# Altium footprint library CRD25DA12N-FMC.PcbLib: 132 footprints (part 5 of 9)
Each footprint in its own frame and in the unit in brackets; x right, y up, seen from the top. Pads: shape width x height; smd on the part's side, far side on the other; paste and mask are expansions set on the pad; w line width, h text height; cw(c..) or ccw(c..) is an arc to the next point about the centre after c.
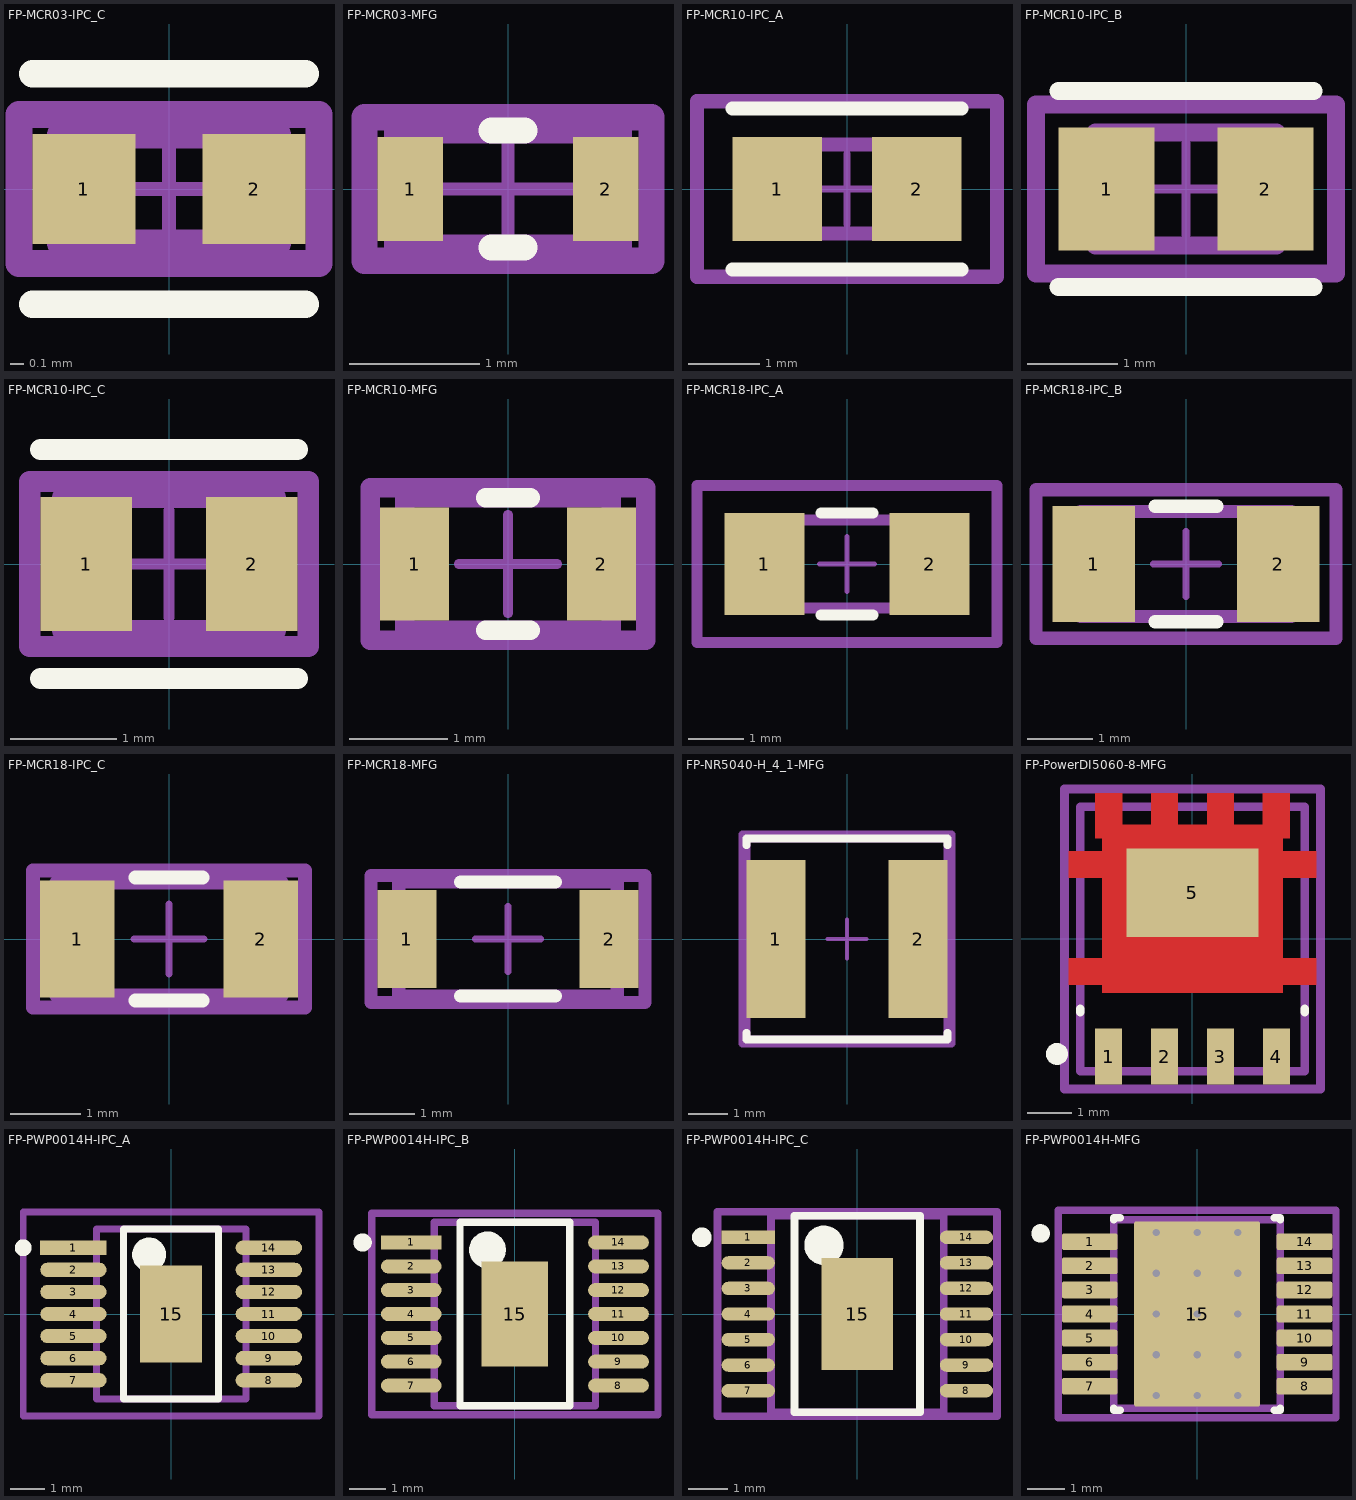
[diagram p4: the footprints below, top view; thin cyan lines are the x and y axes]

## FP-MCR03-IPC_C [mm]
pads (2):
  rect 0.758x0.812 smd paste+0 mask+0: 1(-0.627,0) 2(0.627,0)
Top Overlay:
  lines w0.2: -1.006,-0.85 1.006,-0.85 ; -1.006,0.85 1.006,0.85
Mechanical 5:
  lines w0.2: -1.106,-0.55 1.106,-0.55 1.106,0.55 -1.106,0.55 -1.106,-0.55
  text ".Designator" at 0,0.188 h1
Mechanical 13:
  lines w0.2: -0.8,-0.4 0.8,-0.4 0.8,0.4 -0.8,0.4 -0.8,-0.4
Mechanical 15:
  lines w0.2: -1.106,-0.55 1.106,-0.55 1.106,0.55 -1.106,0.55 -1.106,-0.55
Mechanical 16:
  lines w0.1: -0.5,0 0.5,0 ; 0,-0.5 0,0.5
3D body "Res_Rohm_MCR03ERTF1182_eec.STEP": height 0.25, standoff 0, extent -1.106,-0.55 1.106,0.55

## FP-MCR03-MFG [mm]
pads (2):
  rect 0.5x0.8 smd paste+0 mask+0: 1(-0.75,0) 2(0.75,0)
Top Overlay:
  lines w0.2: -0.125,-0.45 0.125,-0.45 ; -0.125,0.45 0.125,0.45
Mechanical 5:
  lines w0.2: -1.1,-0.55 -1.1,0.55 1.1,0.55 1.1,-0.55 -1.1,-0.55
  text ".Designator" at 0,0.188 h1
Mechanical 13:
  lines w0.2: -0.85,-0.45 -0.85,0.45 0.85,0.45 0.85,-0.45 -0.85,-0.45
Mechanical 15:
  lines w0.2: -1.1,-0.55 -1.1,0.55 1.1,0.55 1.1,-0.55 -1.1,-0.55
Mechanical 16:
  lines w0.1: -0.5,0 0.5,0 ; 0,-0.5 0,0.5
3D body "Res_Rohm_MCR03ERTF1182_eec.STEP": height 0.25, standoff 0, extent -1.1,-0.55 1.1,0.55

## FP-MCR10-IPC_A [mm]
pads (2):
  rect 1.258x1.462 smd paste+0 mask+0: 1(-0.977,0) 2(0.977,0)
Top Overlay:
  lines w0.2: -1.606,-1.131 1.606,-1.131 ; -1.606,1.131 1.606,1.131
Mechanical 5:
  lines w0.2: -2.106,-1.231 2.106,-1.231 2.106,1.231 -2.106,1.231 -2.106,-1.231
  text ".Designator" at 0,0.188 h1
Mechanical 13:
  lines w0.2: -1,-0.625 1,-0.625 1,0.625 -1,0.625 -1,-0.625
Mechanical 15:
  lines w0.2: -2.106,-1.231 2.106,-1.231 2.106,1.231 -2.106,1.231 -2.106,-1.231
Mechanical 16:
  lines w0.1: -0.5,0 0.5,0 ; 0,-0.5 0,0.5
3D body "Res_Rohm_MCR10ERTJ510_eec.STEP": height 0.25, standoff 0, extent -2.106,-1.231 2.106,1.231

## FP-MCR10-IPC_B [mm]
pads (2):
  rect 1.058x1.362 smd paste+0 mask+0: 1(-0.877,0) 2(0.877,0)
Top Overlay:
  lines w0.2: -1.406,-1.081 1.406,-1.081 ; -1.406,1.081 1.406,1.081
Mechanical 5:
  lines w0.2: -1.656,-0.931 1.656,-0.931 1.656,0.931 -1.656,0.931 -1.656,-0.931
  text ".Designator" at 0,0.188 h1
Mechanical 13:
  lines w0.2: -1,-0.625 1,-0.625 1,0.625 -1,0.625 -1,-0.625
Mechanical 15:
  lines w0.2: -1.656,-0.931 1.656,-0.931 1.656,0.931 -1.656,0.931 -1.656,-0.931
Mechanical 16:
  lines w0.1: -0.5,0 0.5,0 ; 0,-0.5 0,0.5
3D body "Res_Rohm_MCR10ERTJ510_eec.STEP": height 0.25, standoff 0, extent -1.656,-0.931 1.656,0.931

## FP-MCR10-IPC_C [mm]
pads (2):
  rect 0.858x1.262 smd paste+0 mask+0: 1(-0.777,0) 2(0.777,0)
Top Overlay:
  lines w0.2: -1.206,-1.075 1.206,-1.075 ; -1.206,1.075 1.206,1.075
Mechanical 5:
  lines w0.2: -1.306,-0.775 -1.306,0.775 1.306,0.775 1.306,-0.775 -1.306,-0.775
  text ".Designator" at 0,0.188 h1
Mechanical 13:
  lines w0.2: -1,-0.625 -1,0.625 1,0.625 1,-0.625 -1,-0.625
Mechanical 15:
  lines w0.2: -1.306,-0.775 -1.306,0.775 1.306,0.775 1.306,-0.775 -1.306,-0.775
Mechanical 16:
  lines w0.1: -0.5,0 0.5,0 ; 0,-0.5 0,0.5
3D body "Res_Rohm_MCR10ERTJ510_eec.STEP": height 0.25, standoff 0, extent -1.306,-0.775 1.306,0.775

## FP-MCR10-MFG [mm]
pads (2):
  rect 0.7x1.15 smd paste+0 mask+0: 1(-0.95,0) 2(0.95,0)
Top Overlay:
  lines w0.2: -0.225,-0.675 0.225,-0.675 ; -0.225,0.675 0.225,0.675
Mechanical 5:
  lines w0.2: -1.4,-0.775 -1.4,0.775 1.4,0.775 1.4,-0.775 -1.4,-0.775
  text ".Designator" at 0,0.188 h1
Mechanical 13:
  lines w0.2: -1.05,-0.675 -1.05,0.675 1.05,0.675 1.05,-0.675 -1.05,-0.675
Mechanical 15:
  lines w0.2: -1.4,-0.775 -1.4,0.775 1.4,0.775 1.4,-0.775 -1.4,-0.775
Mechanical 16:
  lines w0.1: -0.5,0 0.5,0 ; 0,-0.5 0,0.5
3D body "Res_Rohm_MCR10ERTJ510_eec.STEP": height 0.25, standoff 0, extent -1.4,-0.775 1.4,0.775

## FP-MCR18-IPC_A [mm]
pads (2):
  rect 1.456x1.858 smd paste+0 mask+0: 1(-1.501,0) 2(1.501,0)
Top Overlay:
  lines w0.2: -0.473,-0.929 0.473,-0.929 ; -0.473,0.929 0.473,0.929
Mechanical 5:
  lines w0.2: -2.729,-1.429 -2.729,1.429 2.729,1.429 2.729,-1.429 -2.729,-1.429
  text ".Designator" at 0,0.188 h1
Mechanical 13:
  lines w0.2: -1.6,-0.8 -1.6,0.8 1.6,0.8 1.6,-0.8 -1.6,-0.8
Mechanical 15:
  lines w0.2: -2.729,-1.429 -2.729,1.429 2.729,1.429 2.729,-1.429 -2.729,-1.429
Mechanical 16:
  lines w0.1: -0.5,0 0.5,0 ; 0,-0.5 0,0.5
3D body "Res_Rohm_MCR18ERTFL1R10_eec.STEP": height 0.25, standoff 0, extent -2.729,-1.429 2.729,1.429

## FP-MCR18-IPC_B [mm]
pads (2):
  rect 1.256x1.758 smd paste+0 mask+0: 1(-1.401,0) 2(1.401,0)
Top Overlay:
  lines w0.2: -0.473,-0.879 0.473,-0.879 ; -0.473,0.879 0.473,0.879
Mechanical 5:
  lines w0.2: -2.279,-1.129 -2.279,1.129 2.279,1.129 2.279,-1.129 -2.279,-1.129
  text ".Designator" at 0,0.188 h1
Mechanical 13:
  lines w0.2: -1.6,-0.8 -1.6,0.8 1.6,0.8 1.6,-0.8 -1.6,-0.8
Mechanical 15:
  lines w0.2: -2.279,-1.129 -2.279,1.129 2.279,1.129 2.279,-1.129 -2.279,-1.129
Mechanical 16:
  lines w0.1: -0.5,0 0.5,0 ; 0,-0.5 0,0.5
3D body "Res_Rohm_MCR18ERTFL1R10_eec.STEP": height 0.25, standoff 0, extent -2.279,-1.129 2.279,1.129

## FP-MCR18-IPC_C [mm]
pads (2):
  rect 1.056x1.658 smd paste+0 mask+0: 1(-1.301,0) 2(1.301,0)
Top Overlay:
  lines w0.2: -0.473,-0.875 0.473,-0.875 ; -0.473,0.875 0.473,0.875
Mechanical 5:
  lines w0.2: -1.929,-0.975 1.929,-0.975 1.929,0.975 -1.929,0.975 -1.929,-0.975
  text ".Designator" at 0,0.188 h1
Mechanical 13:
  lines w0.2: -1.6,-0.8 1.6,-0.8 1.6,0.8 -1.6,0.8 -1.6,-0.8
Mechanical 15:
  lines w0.2: -1.929,-0.975 1.929,-0.975 1.929,0.975 -1.929,0.975 -1.929,-0.975
Mechanical 16:
  lines w0.1: -0.5,0 0.5,0 ; 0,-0.5 0,0.5
3D body "Res_Rohm_MCR18ERTFL1R10_eec.STEP": height 0.25, standoff 0, extent -1.929,-0.975 1.929,0.975

## FP-MCR18-MFG [mm]
pads (2):
  rect 0.9x1.5 smd paste+0 mask+0: 1(-1.55,0) 2(1.55,0)
Top Overlay:
  lines w0.2: -0.725,-0.875 0.725,-0.875 ; -0.725,0.875 0.725,0.875
Mechanical 5:
  lines w0.2: -2.1,-0.975 -2.1,0.975 2.1,0.975 2.1,-0.975 -2.1,-0.975
  text ".Designator" at 0,0.188 h1
Mechanical 13:
  lines w0.2: -1.675,-0.875 -1.675,0.875 1.675,0.875 1.675,-0.875 -1.675,-0.875
Mechanical 15:
  lines w0.2: -2.1,-0.975 -2.1,0.975 2.1,0.975 2.1,-0.975 -2.1,-0.975
Mechanical 16:
  lines w0.1: -0.5,0 0.5,0 ; 0,-0.5 0,0.5
3D body "Res_Rohm_MCR18ERTFL1R10_eec.STEP": height 0.25, standoff 0, extent -2.1,-0.975 2.1,0.975

## FP-NR5040-H_4_1-MFG [mm]
pads (2):
  rect 1.5x4 smd paste+0 mask+0: 1(-1.8,0) 2(1.8,0)
Top Overlay:
  lines w0.2: -2.55,-2.375 -2.55,-2.55 2.55,-2.55 2.55,-2.375 ; -2.55,2.375 -2.55,2.55 2.55,2.55 2.55,2.375
Mechanical 5:
  lines w0.2: -2.65,-2.65 -2.65,2.65 2.65,2.65 2.65,-2.65 -2.65,-2.65
  text ".Designator" at 0,0.188 h1
Mechanical 13:
  lines w0.2: -2.55,-2.55 -2.55,2.55 2.55,2.55 2.55,-2.55 -2.55,-2.55
Mechanical 15:
  lines w0.2: -2.65,-2.65 -2.65,2.65 2.65,2.65 2.65,-2.65 -2.65,-2.65
Mechanical 16:
  lines w0.1: -0.5,0 0.5,0 ; 0,-0.5 0,0.5
3D body "Ind_Taiyo_Yuden_NR5040T1R5N_eec.STEP": height 0.25, standoff 0, extent -2.65,-2.65 2.65,2.65

## FP-PowerDI5060-8-MFG [mm]
pads (5):
  rect 0.61x1.27 smd paste+0 mask+0: 1(-1.905,-2.67) 2(-0.635,-2.67) 3(0.635,-2.67) 4(1.905,-2.67)
  rect 3x2 smd paste+0 mask+0: 5(0,1.05)
Top Layer:
  region: 2.05,-1.215 -2.05,-1.215 -2.05,-1.035 -2.805,-1.035 -2.805,-0.435 -2.05,-0.435 -2.05,1.39 -2.805,1.39 -2.805,1.99 -2.05,1.99 -2.05,2.285 -2.21,2.285 -2.21,3.305 -1.6,3.305 -1.6,2.595 -0.94,2.595 -0.94,3.305 -0.33,3.305 -0.33,2.595 0.33,2.595 0.33,3.305 0.94,3.305 0.94,2.595 1.6,2.595 1.6,3.305 2.21,3.305 2.21,2.285 2.05,2.285 2.05,1.99 2.805,1.99 2.805,1.39 2.05,1.39 2.05,-0.435 2.805,-0.435 2.805,-1.035 2.05,-1.035
Top Overlay:
  circle w0.25: c-3.075,-2.61 r0.125
  lines w0.2: -2.55,-1.66 -2.55,-1.59 ; 2.55,-1.66 2.55,-1.59
Mechanical 5:
  lines w0.2: -2.905,-3.405 2.905,-3.405 2.905,3.405 -2.905,3.405 -2.905,-3.405
  text ".Designator" at 0,0.188 h1
Mechanical 13:
  lines w0.2: -2.55,-3 2.55,-3 2.55,3 -2.55,3 -2.55,-3
Mechanical 15:
  lines w0.2: -2.905,-3.405 2.905,-3.405 2.905,3.405 -2.905,3.405 -2.905,-3.405
Mechanical 16:
  lines w0.1: -0.5,0 0.5,0 ; 0,-0.5 0,0.5
3D body "Trans_Diodes_DMT12H007LPS-13_eec.STEP": height 0.25, standoff 0, extent -2.905,-3.405 2.905,3.405

## FP-PWP0014H-IPC_A [mm]
pads (15):
  rect 1.955x0.421 smd paste+0 mask+0: 1(-2.875,1.95)
  rrect100% 1.955x0.421 smd paste+0 mask+0: 2(-2.875,1.3) 3(-2.875,0.65) 4(-2.875,0) 5(-2.875,-0.65) 6(-2.875,-1.3) 7(-2.875,-1.95) 8(2.875,-1.95) 9(2.875,-1.3) 10(2.875,-0.65) 11(2.875,0) 12(2.875,0.65) 13(2.875,1.3) 14(2.875,1.95)
  rect 1.82x2.86 smd paste-1000 mask+0: 15(0,0)
Top Overlay:
  circle w0.5: c-0.648,1.75 r0.25
  circle w0.25: c-4.353,1.95 r0.125
  lines w0.2: -1.398,-2.5 1.398,-2.5 1.398,2.5 -1.398,2.5 -1.398,-2.5
Top Paste:
  rectangle: -0.507,-1.027 0.507,1.027
Mechanical 5:
  lines w0.2: -4.353,-3 4.353,-3 4.353,3 -4.353,3 -4.353,-3
  text ".Designator" at 0,0.188 h1
Mechanical 13:
  lines w0.2: -2.2,-2.5 2.2,-2.5 2.2,2.5 -2.2,2.5 -2.2,-2.5
Mechanical 15:
  lines w0.2: -4.353,-3 4.353,-3 4.353,3 -4.353,3 -4.353,-3
Mechanical 16:
  lines w0.1: -0.5,0 0.5,0 ; 0,-0.5 0,0.5
3D body "IC_Texas_Instruments_ALM2402FQPWPRQ1_eec.STEP": height 0.25, standoff 0, extent -4.353,-3 4.353,3

## FP-PWP0014H-IPC_B [mm]
pads (15):
  rect 1.655x0.381 smd paste+0 mask+0: 1(-2.825,1.95)
  rrect100% 1.655x0.381 smd paste+0 mask+0: 2(-2.825,1.3) 3(-2.825,0.65) 4(-2.825,0) 5(-2.825,-0.65) 6(-2.825,-1.3) 7(-2.825,-1.95) 8(2.825,-1.95) 9(2.825,-1.3) 10(2.825,-0.65) 11(2.825,0) 12(2.825,0.65) 13(2.825,1.3) 14(2.825,1.95)
  rect 1.82x2.86 smd paste-1000 mask+0: 15(0,0)
Top Overlay:
  circle w0.5: c-0.748,1.75 r0.25
  circle w0.25: c-4.153,1.95 r0.125
  lines w0.2: -1.498,-2.5 1.498,-2.5 1.498,2.5 -1.498,2.5 -1.498,-2.5
Top Paste:
  rectangle: -0.507,-1.027 0.507,1.027
Mechanical 5:
  lines w0.2: -3.903,-2.75 3.903,-2.75 3.903,2.75 -3.903,2.75 -3.903,-2.75
  text ".Designator" at 0,0.188 h1
Mechanical 13:
  lines w0.2: -2.2,-2.5 2.2,-2.5 2.2,2.5 -2.2,2.5 -2.2,-2.5
Mechanical 15:
  lines w0.2: -3.903,-2.75 3.903,-2.75 3.903,2.75 -3.903,2.75 -3.903,-2.75
Mechanical 16:
  lines w0.1: -0.5,0 0.5,0 ; 0,-0.5 0,0.5
3D body "IC_Texas_Instruments_ALM2402FQPWPRQ1_eec.STEP": height 0.25, standoff 0, extent -3.903,-2.75 3.903,2.75

## FP-PWP0014H-IPC_C [mm]
pads (15):
  rect 1.355x0.341 smd paste+0 mask+0: 1(-2.775,1.95)
  rrect100% 1.355x0.341 smd paste+0 mask+0: 2(-2.775,1.3) 3(-2.775,0.65) 4(-2.775,0) 5(-2.775,-0.65) 6(-2.775,-1.3) 7(-2.775,-1.95) 8(2.775,-1.95) 9(2.775,-1.3) 10(2.775,-0.65) 11(2.775,0) 12(2.775,0.65) 13(2.775,1.3) 14(2.775,1.95)
  rect 1.82x2.86 smd paste-1000 mask+0: 15(0,0)
Top Overlay:
  circle w0.5: c-0.848,1.75 r0.25
  circle w0.25: c-3.953,1.95 r0.125
  lines w0.2: -1.598,-2.5 1.598,-2.5 1.598,2.5 -1.598,2.5 -1.598,-2.5
Top Paste:
  rectangle: -0.507,-1.027 0.507,1.027
Mechanical 5:
  lines w0.2: -3.553,-2.6 3.553,-2.6 3.553,2.6 -3.553,2.6 -3.553,-2.6
  text ".Designator" at 0,0.188 h1
Mechanical 13:
  lines w0.2: -2.2,-2.5 2.2,-2.5 2.2,2.5 -2.2,2.5 -2.2,-2.5
Mechanical 15:
  lines w0.2: -3.553,-2.6 3.553,-2.6 3.553,2.6 -3.553,2.6 -3.553,-2.6
Mechanical 16:
  lines w0.1: -0.5,0 0.5,0 ; 0,-0.5 0,0.5
3D body "IC_Texas_Instruments_ALM2402FQPWPRQ1_eec.STEP": height 0.25, standoff 0, extent -3.553,-2.6 3.553,2.6

## FP-PWP0014H-MFG [mm]
pads (15):
  rrect22% 1.5x0.45 smd paste+0 mask+0: 1(-2.9,1.95) 2(-2.9,1.3) 3(-2.9,0.65) 4(-2.9,0) 5(-2.9,-0.65) 6(-2.9,-1.3) 7(-2.9,-1.95) 8(2.9,-1.95) 9(2.9,-1.3) 10(2.9,-0.65) 11(2.9,0) 12(2.9,0.65) 13(2.9,1.3) 14(2.9,1.95)
  rrect3% 3.4x5 smd paste-1000 mask-1000: 15(0,0)
via 1.1,2.2 diameter 0.5 hole 0.2
via 1.1,1.1 diameter 0.5 hole 0.2
via 1.1,0 diameter 0.5 hole 0.2
via 1.1,-1.1 diameter 0.5 hole 0.2
via 1.1,-2.2 diameter 0.5 hole 0.2
via -1.1,2.2 diameter 0.5 hole 0.2
via -1.1,1.1 diameter 0.5 hole 0.2
via -1.1,0 diameter 0.5 hole 0.2
via -1.1,-1.1 diameter 0.5 hole 0.2
via -1.1,-2.2 diameter 0.5 hole 0.2
via 0,2.2 diameter 0.5 hole 0.2
via 0,1.1 diameter 0.5 hole 0.2
via 0,0 diameter 0.5 hole 0.2
via 0,-1.1 diameter 0.5 hole 0.2
via 0,-2.2 diameter 0.5 hole 0.2
Top Overlay:
  circle w0.25: c-4.225,2.175 r0.125
  lines w0.2: -2.25,-2.55 -2.25,-2.6 -2.075,-2.6 ; -2.25,2.55 -2.25,2.6 -2.075,2.6 ; 2.075,-2.6 2.25,-2.6 2.25,-2.55 ; 2.075,2.6 2.25,2.6 2.25,2.55
Top Paste:
  region: 0.91,1.38 0.91,-1.38 0.91,-1.39 0.902,-1.408 0.888,-1.422 0.87,-1.43 0.86,-1.43 -0.86,-1.43 -0.87,-1.43 -0.888,-1.422 -0.902,-1.408 -0.91,-1.39 -0.91,-1.38 -0.91,1.38 -0.91,1.39 -0.902,1.408 -0.888,1.422 -0.87,1.43 -0.86,1.43 0.86,1.43 0.87,1.43 0.888,1.422 0.902,1.408 0.91,1.39
Top Solder:
  region: 0.91,1.38 0.91,-1.38 0.91,-1.39 0.902,-1.408 0.888,-1.422 0.87,-1.43 0.86,-1.43 -0.86,-1.43 -0.87,-1.43 -0.888,-1.422 -0.902,-1.408 -0.91,-1.39 -0.91,-1.38 -0.91,1.38 -0.91,1.39 -0.902,1.408 -0.888,1.422 -0.87,1.43 -0.86,1.43 0.86,1.43 0.87,1.43 0.888,1.422 0.902,1.408 0.91,1.39
Mechanical 5:
  lines w0.2: -3.75,-2.8 3.75,-2.8 3.75,2.8 -3.75,2.8 -3.75,-2.8
  text ".Designator" at 0,0.188 h1
Mechanical 13:
  lines w0.2: -2.25,-2.55 2.25,-2.55 2.25,2.55 -2.25,2.55 -2.25,-2.55
Mechanical 15:
  lines w0.2: -3.75,-2.8 3.75,-2.8 3.75,2.8 -3.75,2.8 -3.75,-2.8
Mechanical 16:
  lines w0.1: -0.5,0 0.5,0 ; 0,-0.5 0,0.5
3D body "IC_Texas_Instruments_ALM2402FQPWPRQ1_eec.STEP": height 0.25, standoff 0, extent -3.75,-2.8 3.75,2.8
